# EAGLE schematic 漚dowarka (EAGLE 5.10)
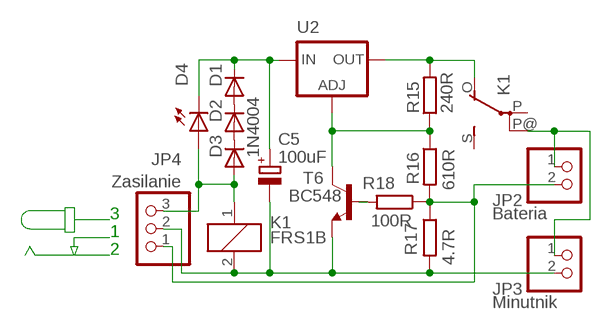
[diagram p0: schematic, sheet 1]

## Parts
C5  100uF  CPOL-EUE2.5-7  [E2,5-7]
D1  1N4004  [DO41-10]
D2  1N4004  [DO41-10]
D3  1N4004  [DO41-10]
D4  LED3MM  [LED3MM]
JP2  Bateria  PINHD-1X2/90  [1X02/90]
JP3  Minutnik  PINHD-1X2/90  [1X02/90]
JP4  Zasilanie  PINHD-1X3/90  [1X03/90]
K1  FRS1B  [FRS1B]
R15  240R  R-EU_0207/7  [0207/7]
R16  610R  R-EU_0207/7  [0207/7]
R17  4.7R  R-EU_0207/7  [0207/7]
R18  100R  R-EU_0207/7  [0207/7]
T6  BC548  BC547  [TO92]
U2  LM317TL  [317TL]

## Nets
N$1: D2.A D3.C
N$2: C5.+ D1.C D4.K(C) U2.3(IN)
N$3: K1.O(2:O) R15.2 U2.2(OUT)
N$4: D3.A D4.A JP4.3 K1.1
N$5: R15.1 R16.1 T6.3(C) U2.1(ADJ)
N$6: JP2.2 JP4.1 R16.2 R17.1 R18.1
N$7: R18.2 T6.2(B)
N$8: C5.- JP3.2 JP4.2 K1.2 R17.2 T6.1(E)
N$9: D1.A D2.C
N$10: JP2.1 JP3.1 K1.P@(2:P)
Unconnected: K1.P(2:P) K1.S(2:S)

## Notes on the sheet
- 3
- 1
- 2

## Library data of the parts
C5 = rcl:CPOL-EU: POLARIZED CAPACITOR, European symbol
D1-D3 = diode:1N4004: DIODE
D4 = led:LED: LED
JP2 JP3 = pinhead:PINHD-1X2: PIN HEADER
JP4 = pinhead:PINHD-1X3: PIN HEADER
K1 = relay:FRS1B: RELAY 1 x switch, same as V23101-D6-A201, Siemens
R15-R18 = rcl:R-EU_: RESISTOR, European symbol
T6 = transistor-neu-to92:BC547: NPN TRANSISTOR
U2 = v-reg:LM317TL: VOLTAGE REGULATOR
